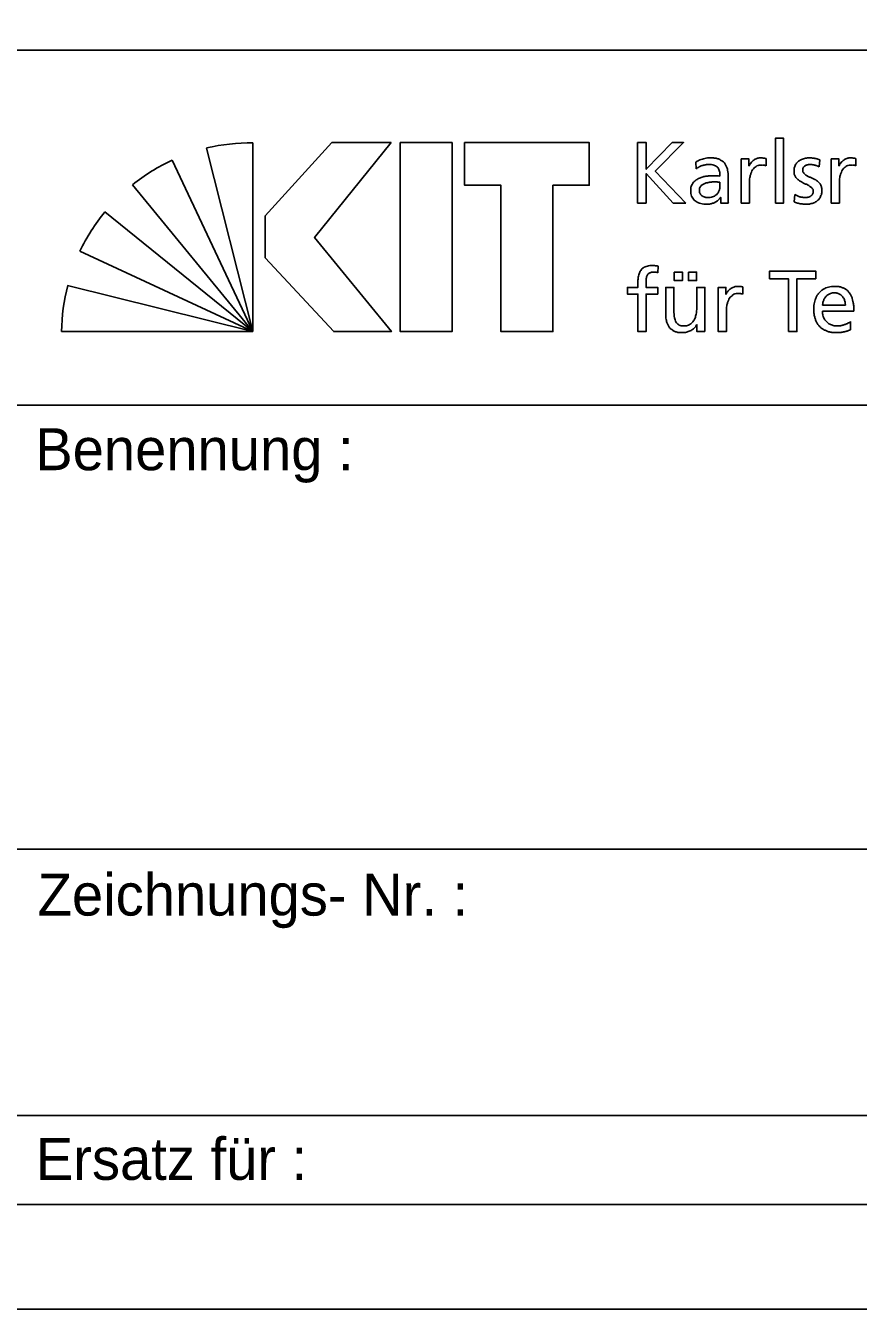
# Model space of a CAD drawing. Extents: x 0 to 148, y 0 to 105.
# Drawn here: x 126.41 to 136.33, y 0 to 15.29 of the extents above; entities that cross this region are included whole.
import ezdxf

# ---------------------------------------------------------------- set-up
doc = ezdxf.new("R2010")
doc.units = 0
doc.layers.add('90_Plankopf', color=7, linetype='Continuous')

msp = doc.modelspace()

# ---------------------------------------------------------------- linework, layer by layer
at = {"layer": '90_Plankopf'}
for p, q in [((102.78, 14.998), (147.25, 14.998)), ((102.78, 14.998), (147.25, 14.998)), ((128.569, 13.833), (129.12, 11.647)), ((129.12, 11.647), (129.12, 13.896)), ((133.702, 13.897), (133.702, 13.176)), ((129.12, 11.647), (128.158, 13.688)), ((134.395, 13.665), (134.4, 13.583)), ((135.232, 13.621), (135.232, 13.708)), ((135.864, 13.61), (135.872, 13.694)), ((136.303, 13.621), (136.303, 13.708)), ((134.78, 13.28), (134.78, 13.497)), ((127.686, 13.396), (129.12, 11.647)), ((134.683, 13.427), (134.683, 13.381)), ((133.702, 13.176), (133.806, 13.176)), ((134.126, 13.176), (134.277, 13.176)), ((135.574, 13.28), (135.569, 13.193)), ((129.12, 11.647), (127.358, 13.071)), ((127.06, 12.603), (129.12, 11.647)), ((133.943, 12.348), (133.947, 12.427)), ((129.12, 11.647), (126.914, 12.197)), ((134.957, 12.091), (134.957, 12.178)), ((136.177, 11.96), (135.904, 11.96)), ((135.904, 11.888), (136.28, 11.888)), ((126.841, 11.647), (129.12, 11.647)), ((136.239, 11.668), (136.239, 11.765)), ((126.25, 10.768), (147.25, 10.768)), ((126.25, 5.48), (147.25, 5.48)), ((126.25, 2.308), (147.25, 2.308)), ((147.25, 1.25), (102.78, 1.25)), ((105.7, 1.25), (147.25, 1.25)), ((105.7, 1.25), (147.25, 1.25))]:
    msp.add_line(p, q, dxfattribs=at)
for points in [[(0, 0), (148.5, 0), (148.5, 105), (0, 105)], [(6.25, 103.75), (147.25, 103.75), (147.25, 1.25), (6.25, 1.25)], [(130.767, 13.897), (130.059, 13.897), (129.268, 13.025), (129.268, 12.523), (130.084, 11.647), (130.771, 11.647), (129.856, 12.766)], [(131.493, 13.897), (131.493, 11.647), (130.875, 11.647), (130.875, 13.897)], [(131.641, 13.897), (131.641, 13.39), (132.075, 13.39), (132.075, 11.647), (132.693, 11.647), (132.693, 13.39), (133.127, 13.39), (133.127, 13.897)]]:
    msp.add_lwpolyline(points, close=True, dxfattribs=at)
for points in [[(135.345, 13.176), (135.442, 13.176), (135.442, 13.95), (135.345, 13.95), (135.345, 13.176)], [(134.277, 13.176), (133.912, 13.556), (134.25, 13.897), (134.113, 13.897), (133.806, 13.58), (133.806, 13.897), (133.702, 13.897)], [(135.03, 13.621), (135.028, 13.621), (135.028, 13.703), (134.938, 13.703), (134.938, 13.176), (135.035, 13.176), (135.035, 13.416)], [(136.102, 13.621), (136.1, 13.621), (136.1, 13.703), (136.009, 13.703), (136.009, 13.176), (136.106, 13.176), (136.106, 13.416)], [(133.806, 13.176), (133.806, 13.529), (134.126, 13.176)], [(134.691, 13.245), (134.693, 13.245), (134.693, 13.176), (134.784, 13.176)], [(134.139, 12.356), (134.139, 12.253), (134.236, 12.253), (134.236, 12.356), (134.139, 12.356)], [(134.308, 12.356), (134.308, 12.253), (134.405, 12.253), (134.405, 12.356), (134.308, 12.356)], [(135.498, 11.647), (135.601, 11.647), (135.601, 12.276), (135.825, 12.276), (135.825, 12.367), (135.274, 12.367), (135.274, 12.276), (135.498, 12.276), (135.498, 11.647)], [(133.706, 12.221), (133.706, 12.173), (133.582, 12.173), (133.582, 12.094), (133.706, 12.094), (133.706, 11.647), (133.803, 11.647), (133.803, 12.094), (133.942, 12.094), (133.942, 12.173), (133.803, 12.173), (133.803, 12.23)], [(134.135, 11.9), (134.135, 12.173), (134.038, 12.173), (134.038, 11.86)], [(134.504, 11.647), (134.504, 12.173), (134.407, 12.173), (134.407, 11.929)], [(134.756, 12.091), (134.754, 12.091), (134.754, 12.173), (134.663, 12.173), (134.663, 11.647), (134.76, 11.647), (134.76, 11.886)], [(134.408, 11.73), (134.41, 11.73), (134.41, 11.647), (134.504, 11.647)]]:
    msp.add_lwpolyline(points, dxfattribs=at)
for centre, start, end in [((129.112, 11.514), 89.8053, 103.1895), ((129.165, 11.529), 115.0126, 128.3968), ((129.204, 11.566), 140.7898, 154.174), ((129.223, 11.609), 165.7222, 179.1064)]:
    msp.add_arc(centre, 2.382, start, end, dxfattribs=at)
for points in [[(134.78, 13.497), (134.78, 13.545), (134.773, 13.585), (134.758, 13.617), (134.744, 13.65), (134.721, 13.674), (134.69, 13.69), (134.659, 13.707), (134.618, 13.715), (134.568, 13.715), (134.535, 13.715), (134.503, 13.71), (134.474, 13.701), (134.445, 13.692), (134.419, 13.68), (134.395, 13.665)], [(134.4, 13.583), (134.413, 13.594), (134.428, 13.604), (134.445, 13.611), (134.461, 13.62), (134.479, 13.626), (134.497, 13.63), (134.516, 13.634), (134.534, 13.637), (134.553, 13.637), (134.585, 13.637), (134.61, 13.631), (134.629, 13.621), (134.649, 13.611), (134.662, 13.596), (134.67, 13.575), (134.679, 13.555), (134.683, 13.53), (134.683, 13.499)], [(135.232, 13.708), (135.225, 13.709), (135.218, 13.71), (135.212, 13.712), (135.206, 13.713), (135.199, 13.713), (135.192, 13.714), (135.185, 13.715), (135.177, 13.715), (135.168, 13.715), (135.149, 13.715), (135.131, 13.711), (135.113, 13.703), (135.095, 13.695), (135.079, 13.684), (135.065, 13.67), (135.051, 13.656), (135.039, 13.639), (135.03, 13.621)], [(135.035, 13.416), (135.035, 13.46), (135.041, 13.498), (135.052, 13.53), (135.064, 13.562), (135.081, 13.587), (135.102, 13.604), (135.124, 13.621), (135.149, 13.63), (135.178, 13.63), (135.186, 13.631), (135.195, 13.63), (135.204, 13.629), (135.214, 13.627), (135.223, 13.625), (135.232, 13.621)], [(135.872, 13.694), (135.854, 13.7), (135.834, 13.705), (135.815, 13.709), (135.795, 13.713), (135.774, 13.715), (135.752, 13.715), (135.726, 13.715), (135.701, 13.712), (135.679, 13.705), (135.656, 13.698), (135.637, 13.688), (135.62, 13.675), (135.603, 13.662), (135.59, 13.645), (135.58, 13.625), (135.571, 13.604), (135.566, 13.58), (135.566, 13.553), (135.566, 13.532), (135.571, 13.514), (135.579, 13.498), (135.587, 13.483), (135.598, 13.47), (135.611, 13.459), (135.625, 13.447), (135.64, 13.437), (135.656, 13.429), (135.672, 13.42), (135.688, 13.412), (135.704, 13.404), (135.721, 13.397), (135.735, 13.389), (135.749, 13.38), (135.762, 13.373), (135.773, 13.363), (135.782, 13.353), (135.79, 13.343), (135.794, 13.331), (135.794, 13.318), (135.794, 13.304), (135.791, 13.292), (135.785, 13.282), (135.779, 13.272), (135.771, 13.265), (135.761, 13.259), (135.751, 13.253), (135.741, 13.249), (135.729, 13.246), (135.718, 13.244), (135.706, 13.242), (135.695, 13.242), (135.685, 13.242), (135.674, 13.244), (135.66, 13.247), (135.646, 13.249), (135.631, 13.253), (135.616, 13.259), (135.601, 13.265), (135.587, 13.271), (135.574, 13.28)], [(135.569, 13.193), (135.592, 13.181), (135.615, 13.174), (135.639, 13.17), (135.664, 13.166), (135.689, 13.164), (135.714, 13.164), (135.737, 13.164), (135.76, 13.167), (135.782, 13.174), (135.804, 13.18), (135.823, 13.191), (135.841, 13.204), (135.858, 13.217), (135.872, 13.234), (135.882, 13.255), (135.892, 13.276), (135.897, 13.3), (135.897, 13.328), (135.897, 13.352), (135.893, 13.372), (135.885, 13.389), (135.876, 13.406), (135.866, 13.42), (135.852, 13.431), (135.839, 13.443), (135.824, 13.453), (135.807, 13.461), (135.791, 13.469), (135.775, 13.477), (135.759, 13.484), (135.743, 13.491), (135.728, 13.499), (135.714, 13.507), (135.701, 13.515), (135.69, 13.524), (135.682, 13.534), (135.674, 13.545), (135.669, 13.557), (135.669, 13.573), (135.669, 13.587), (135.674, 13.599), (135.682, 13.609), (135.691, 13.618), (135.702, 13.625), (135.716, 13.63), (135.73, 13.634), (135.745, 13.637), (135.762, 13.637), (135.768, 13.637), (135.776, 13.636), (135.785, 13.634), (135.794, 13.633), (135.803, 13.631), (135.814, 13.628), (135.824, 13.626), (135.833, 13.623), (135.842, 13.62), (135.851, 13.616), (135.859, 13.613), (135.864, 13.61)], [(136.303, 13.708), (136.296, 13.709), (136.29, 13.71), (136.284, 13.712), (136.277, 13.713), (136.271, 13.713), (136.264, 13.714), (136.257, 13.715), (136.248, 13.715), (136.239, 13.715), (136.22, 13.715), (136.202, 13.711), (136.184, 13.703), (136.167, 13.695), (136.151, 13.684), (136.136, 13.67), (136.122, 13.656), (136.11, 13.639), (136.102, 13.621)], [(136.106, 13.416), (136.106, 13.46), (136.112, 13.498), (136.124, 13.53), (136.136, 13.562), (136.152, 13.587), (136.173, 13.604), (136.195, 13.621), (136.22, 13.63), (136.249, 13.63), (136.258, 13.631), (136.266, 13.63), (136.276, 13.629), (136.285, 13.627), (136.294, 13.625), (136.303, 13.621)], [(134.683, 13.499), (134.67, 13.5), (134.658, 13.501), (134.647, 13.501), (134.636, 13.501), (134.626, 13.501), (134.615, 13.501), (134.604, 13.501), (134.592, 13.501), (134.579, 13.501), (134.559, 13.501), (134.538, 13.5), (134.516, 13.496), (134.493, 13.492), (134.471, 13.487), (134.45, 13.478), (134.429, 13.47), (134.41, 13.46), (134.392, 13.446), (134.375, 13.433), (134.361, 13.416), (134.351, 13.397), (134.34, 13.377), (134.335, 13.354), (134.335, 13.328), (134.335, 13.29), (134.344, 13.259), (134.36, 13.235), (134.376, 13.211), (134.399, 13.193), (134.427, 13.181), (134.456, 13.17), (134.49, 13.164), (134.528, 13.164), (134.55, 13.164), (134.57, 13.167), (134.588, 13.172), (134.605, 13.177), (134.621, 13.184), (134.634, 13.192), (134.648, 13.2), (134.659, 13.209), (134.668, 13.218), (134.678, 13.228), (134.685, 13.236), (134.691, 13.245)], [(134.683, 13.381), (134.683, 13.354), (134.677, 13.331), (134.666, 13.31), (134.655, 13.289), (134.638, 13.273), (134.617, 13.261), (134.595, 13.249), (134.568, 13.243), (134.536, 13.242), (134.525, 13.242), (134.514, 13.244), (134.502, 13.248), (134.491, 13.252), (134.48, 13.257), (134.47, 13.264), (134.461, 13.272), (134.453, 13.281), (134.447, 13.291), (134.441, 13.302), (134.438, 13.314), (134.438, 13.328), (134.438, 13.347), (134.443, 13.362), (134.452, 13.374), (134.461, 13.387), (134.473, 13.396), (134.487, 13.404), (134.502, 13.411), (134.517, 13.417), (134.534, 13.42), (134.55, 13.424), (134.566, 13.426), (134.582, 13.428), (134.597, 13.429), (134.61, 13.429), (134.621, 13.429), (134.631, 13.429), (134.641, 13.429), (134.652, 13.428), (134.662, 13.428), (134.672, 13.427), (134.683, 13.427)], [(134.784, 13.176), (134.783, 13.181), (134.782, 13.188), (134.782, 13.197), (134.781, 13.205), (134.781, 13.216), (134.78, 13.23), (134.78, 13.243), (134.78, 13.26), (134.78, 13.28)], [(133.947, 12.427), (133.938, 12.428), (133.928, 12.43), (133.917, 12.431), (133.906, 12.432), (133.895, 12.433), (133.882, 12.433), (133.847, 12.433), (133.818, 12.428), (133.794, 12.418), (133.771, 12.408), (133.753, 12.394), (133.741, 12.375), (133.728, 12.356), (133.719, 12.334), (133.714, 12.308), (133.708, 12.282), (133.706, 12.253), (133.706, 12.221)], [(133.803, 12.23), (133.803, 12.247), (133.804, 12.264), (133.806, 12.279), (133.808, 12.294), (133.812, 12.307), (133.819, 12.319), (133.825, 12.33), (133.835, 12.339), (133.847, 12.345), (133.86, 12.351), (133.876, 12.354), (133.897, 12.354), (133.905, 12.354), (133.914, 12.354), (133.922, 12.353), (133.93, 12.352), (133.938, 12.35), (133.943, 12.348)], [(134.957, 12.178), (134.95, 12.179), (134.943, 12.181), (134.938, 12.182), (134.931, 12.183), (134.925, 12.184), (134.917, 12.184), (134.911, 12.185), (134.902, 12.185), (134.893, 12.185), (134.874, 12.185), (134.856, 12.181), (134.838, 12.173), (134.821, 12.165), (134.805, 12.154), (134.79, 12.14), (134.776, 12.126), (134.764, 12.11), (134.756, 12.091)], [(134.76, 11.886), (134.76, 11.93), (134.766, 11.968), (134.778, 12), (134.789, 12.032), (134.806, 12.057), (134.827, 12.074), (134.849, 12.092), (134.874, 12.1), (134.903, 12.1), (134.912, 12.101), (134.92, 12.1), (134.93, 12.099), (134.939, 12.097), (134.948, 12.095), (134.957, 12.091)], [(136.28, 11.888), (136.28, 11.931), (136.276, 11.97), (136.268, 12.006), (136.26, 12.042), (136.247, 12.073), (136.229, 12.1), (136.211, 12.127), (136.188, 12.148), (136.158, 12.162), (136.128, 12.177), (136.091, 12.185), (136.047, 12.185), (136.01, 12.185), (135.976, 12.178), (135.946, 12.166), (135.916, 12.152), (135.89, 12.134), (135.868, 12.111), (135.847, 12.087), (135.83, 12.059), (135.819, 12.026), (135.807, 11.994), (135.801, 11.958), (135.801, 11.919), (135.801, 11.876), (135.806, 11.837), (135.817, 11.802), (135.828, 11.767), (135.845, 11.737), (135.867, 11.712), (135.889, 11.687), (135.918, 11.668), (135.952, 11.655), (135.986, 11.641), (136.027, 11.634), (136.073, 11.634), (136.102, 11.634), (136.126, 11.636), (136.147, 11.64), (136.167, 11.644), (136.184, 11.648), (136.199, 11.653), (136.214, 11.659), (136.227, 11.664), (136.239, 11.668)], [(135.904, 11.96), (135.906, 11.977), (135.91, 11.995), (135.916, 12.012), (135.922, 12.029), (135.931, 12.045), (135.942, 12.059), (135.953, 12.073), (135.967, 12.085), (135.984, 12.093), (136.001, 12.102), (136.022, 12.107), (136.045, 12.107), (136.066, 12.107), (136.085, 12.103), (136.101, 12.095), (136.117, 12.088), (136.131, 12.077), (136.142, 12.064), (136.153, 12.05), (136.162, 12.035), (136.168, 12.017), (136.174, 11.999), (136.177, 11.981), (136.177, 11.96)], [(134.407, 11.929), (134.407, 11.897), (134.404, 11.868), (134.397, 11.841), (134.391, 11.815), (134.381, 11.792), (134.368, 11.773), (134.355, 11.754), (134.338, 11.739), (134.318, 11.728), (134.298, 11.718), (134.274, 11.713), (134.247, 11.713), (134.219, 11.714), (134.197, 11.722), (134.18, 11.736), (134.164, 11.75), (134.152, 11.771), (134.145, 11.798), (134.139, 11.825), (134.135, 11.859), (134.135, 11.9)], [(134.038, 11.86), (134.038, 11.813), (134.045, 11.772), (134.059, 11.739), (134.073, 11.705), (134.095, 11.679), (134.124, 11.661), (134.153, 11.644), (134.19, 11.634), (134.236, 11.634), (134.26, 11.634), (134.284, 11.638), (134.306, 11.646), (134.329, 11.653), (134.349, 11.665), (134.367, 11.679), (134.384, 11.693), (134.398, 11.71), (134.408, 11.73)], [(136.239, 11.765), (136.233, 11.76), (136.225, 11.755), (136.213, 11.749), (136.202, 11.743), (136.189, 11.737), (136.174, 11.732), (136.159, 11.726), (136.143, 11.722), (136.126, 11.718), (136.11, 11.715), (136.094, 11.713), (136.077, 11.713), (136.054, 11.713), (136.032, 11.717), (136.012, 11.725), (135.991, 11.734), (135.972, 11.746), (135.956, 11.761), (135.94, 11.777), (135.927, 11.795), (135.918, 11.817), (135.909, 11.838), (135.904, 11.862), (135.904, 11.888)]]:
    msp.add_open_spline(points, degree=3, dxfattribs=at)

# ---------------------------------------------------------------- texts
for s, p in [('Benennung :', (126.528, 9.995)), ('Zeichnungs- Nr. :', (126.557, 4.69)), ('Ersatz für :', (126.535, 1.542))]:
    msp.add_text(s, height=0.5, dxfattribs=at).set_placement(p)

doc.saveas('drawing.dxf')
